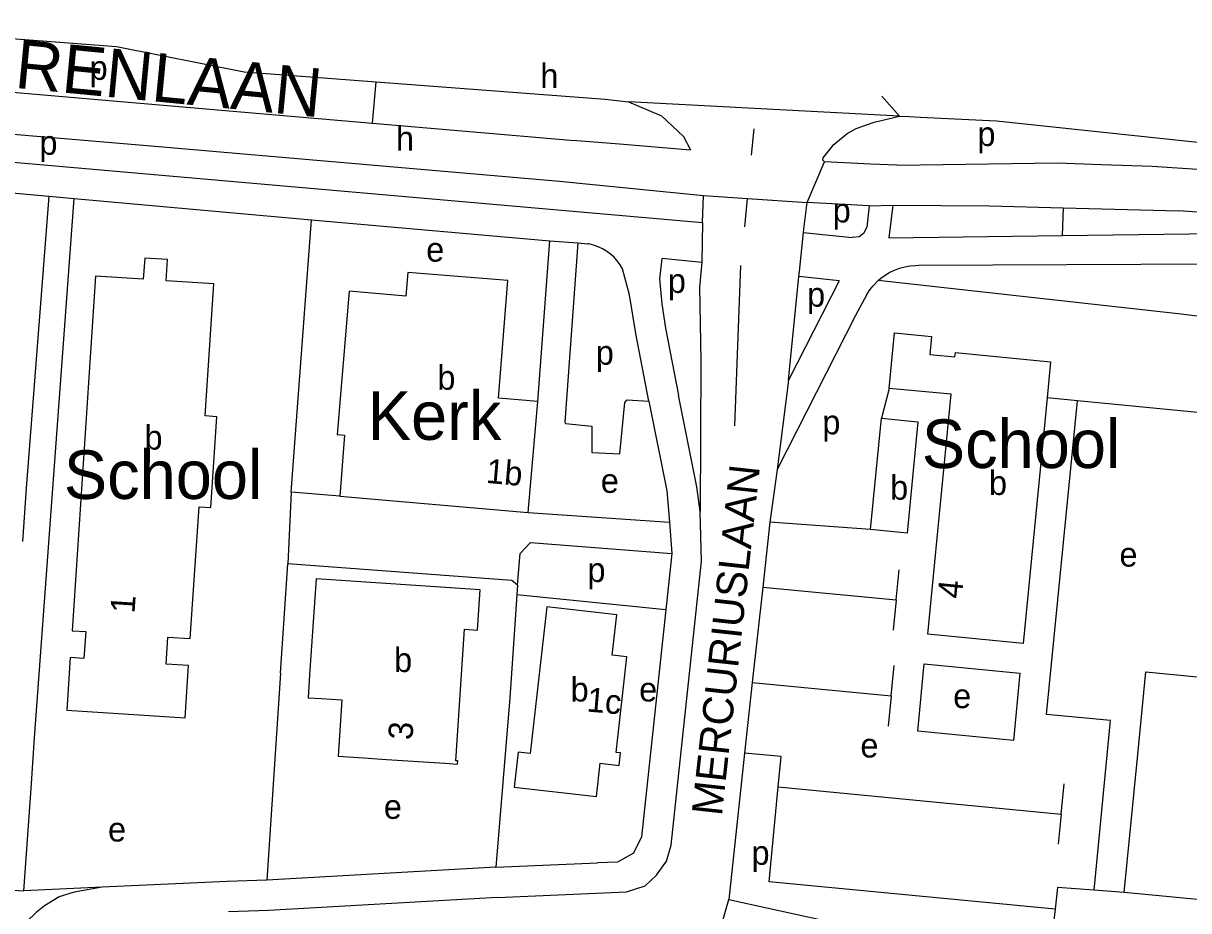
# Model space of a CAD drawing. Extents: x 161773 to 163836, y 384796 to 386521.
# Drawn here: x 162054.9 to 162246.8, y 386359.1 to 386505.2 of the extents above; entities that cross this region are included whole.
import ezdxf

# ---------------------------------------------------------------- set-up
doc = ezdxf.new("R2010")
doc.units = 0
for name, color, linetype in [('BLT_Basislijn', 7, 'Continuous'), ('BLT_Bebouwing', 7, 'Continuous'), ('BLT_Bebouwing_beschrifting', 7, 'Continuous'), ('BLT_Centroide', 7, 'Continuous'), ('BLT_Huisnummer', 7, 'Continuous'), ('BLT_Straatnaam', 7, 'Continuous'), ('BLT_Straatnaam_hoofdweg', 7, 'Continuous'), ('BLT_Vlakafsluiter', 7, 'Continuous')]:
    doc.layers.add(name, color=color, linetype=linetype)

msp = doc.modelspace()

# ---------------------------------------------------------------- linework, layer by layer
at = {"layer": 'BLT_Basislijn'}
for p, q in [((162112.37, 386488.77), (162112.99, 386495.59)), ((162077.31, 386491.77), (162112.37, 386488.77)), ((162002.79, 386491.19), (162077.21, 386484.92)), ((162112.37, 386488.77), (162145, 386485.99)), ((162174.81, 386483.48), (162175.23, 386487.81)), ((162145, 386485.99), (162146.03, 386485.91)), ((162146.03, 386485.91), (162153.05, 386485.37)), ((162077.21, 386484.92), (162143.18, 386479.23)), ((162153.05, 386485.37), (162164.77, 386484.39)), ((162004.3, 386481.62), (162059.08, 386476.74)), ((162143.18, 386479.23), (162166.9, 386476.88)), ((162059.08, 386476.74), (162055.37, 386428.67)), ((162059.08, 386476.74), (162063.26, 386476.36)), ((162060.46, 386438.36), (162063.26, 386476.36)), ((162063.26, 386476.36), (162102.35, 386472.88)), ((162166.71, 386472.43), (162166.9, 386476.88)), ((162173.67, 386471.69), (162174.12, 386476.38)), ((162194.19, 386475.17), (162183.94, 386475.71)), ((162194.19, 386475.17), (162198.04, 386475.28)), ((162226.12, 386474.85), (162225.92, 386470.26)), ((162226.12, 386474.85), (162245.23, 386474.34)), ((162098.98, 386428), (162102.35, 386472.88)), ((162102.35, 386472.88), (162141.6, 386469.4)), ((162266.83, 386472.75), (162245.23, 386474.34)), ((162166.71, 386472.43), (162166.62, 386465.81)), ((162183.33, 386470.77), (162191.39, 386469.94)), ((162225.92, 386470.26), (162252.74, 386470.61)), ((162139.58, 386442.97), (162141.6, 386469.4)), ((162141.6, 386469.4), (162146.17, 386469.04)), ((162146.17, 386469.04), (162147.85, 386468.91)), ((162172.06, 386438.96), (162173.06, 386465.35)), ((162202.35, 386465.37), (162252.34, 386465.63)), ((162189.2, 386462.82), (162182.58, 386463.52)), ((162189.2, 386462.82), (162180.89, 386446.48)), ((162193.8, 386460.58), (162191.89, 386457.08)), ((162191.89, 386457.08), (162178.99, 386431.72)), ((162180.89, 386446.48), (162178.99, 386431.72)), ((162197.46, 386445.11), (162196.17, 386440.2)), ((162223.39, 386391.42), (162228.45, 386443.04)), ((162228.45, 386443.04), (162223.47, 386443.53)), ((162178.99, 386431.72), (162177.82, 386423.1)), ((162055.37, 386428.67), (162054.77, 386419.92)), ((162138.03, 386424.67), (162161.31, 386423.05)), ((162166.57, 386416.66), (162166.33, 386424.82)), ((162161.31, 386423.05), (162161.69, 386417.91)), ((162177.82, 386423.1), (162176.64, 386412.37)), ((162194.41, 386421.85), (162177.82, 386423.1)), ((162161.69, 386417.91), (162160.68, 386408.62)), ((162097.25, 386398.22), (162098.45, 386416.24)), ((162198.62, 386410.27), (162199.1, 386415.24)), ((162136.26, 386412.69), (162136.15, 386411.09)), ((162160.68, 386408.62), (162136.15, 386411.09)), ((162176.64, 386412.37), (162174.92, 386396.68)), ((162176.64, 386412.37), (162198.62, 386410.27)), ((162198.62, 386410.27), (162198.14, 386405.29)), ((162097.25, 386398.22), (162094.98, 386364.12)), ((162197.79, 386394.49), (162198.26, 386399.46)), ((162174.92, 386396.68), (162173.66, 386385.07)), ((162174.9, 386396.68), (162197.79, 386394.49)), ((162197.79, 386394.49), (162197.31, 386389.51)), ((162173.66, 386385.07), (162171.05, 386360.94)), ((162054.99, 386362.39), (162056.16, 386379.24)), ((162179.2, 386379.49), (162225.77, 386375.02)), ((162225.77, 386375.02), (162226.25, 386380)), ((162225.77, 386375.02), (162225.29, 386370.04)), ((162132.71, 386366.26), (162149.44, 386366.99)), ((162132.71, 386366.26), (162094.98, 386364.12)), ((162088.45, 386363.89), (162067.88, 386362.97)), ((162094.98, 386364.12), (162088.45, 386363.89)), ((162052.3, 386362.57), (162054.99, 386362.39)), ((162067.88, 386362.97), (162054.99, 386362.39)), ((162132.96, 386361.27), (162154.23, 386362.2)), ((162225.19, 386362.94), (162224.77, 386359.37)), ((162231.2, 386362.5), (162225.19, 386362.94)), ((162236.18, 386362.13), (162231.2, 386362.5)), ((162224.77, 386359.37), (162223.74, 386350.72))]:
    msp.add_line(p, q, dxfattribs=at)
for points in [[(162046.31, 386502.96), (162053, 386502.69), (162070.25, 386501.37), (162091.27, 386497.24), (162112.99, 386495.59)], [(162003.09, 386498.13), (162015.49, 386497.13), (162077.31, 386491.77)], [(162112.99, 386495.59), (162150.72, 386492.73), (162154.52, 386492.27)], [(162154.52, 386492.27), (162159.98, 386489.95), (162163.58, 386486.57), (162164.77, 386484.39)], [(162186.79, 386482.38), (162186.56, 386482.67), (162186.61, 386483.04), (162188.36, 386485.27), (162190.56, 386487.07), (162192, 386487.88), (162195.01, 386488.92), (162199.14, 386489.93)], [(162199.14, 386489.93), (162200.76, 386489.85)], [(162200.76, 386489.85), (162202.54, 386489.78), (162215.14, 386489.16), (162251.92, 386485.23), (162266.39, 386484.28), (162278.05, 386481.5), (162301.92, 386479.18)], [(162002.53, 386486.84), (162003.63, 386486.7), (162166.71, 386472.43)], [(162198.78, 386481.86), (162194.36, 386482), (162186.79, 386482.38)], [(162198.78, 386481.86), (162225.1, 386482.22), (162232.41, 386481.99), (162240.77, 386481.69), (162249.05, 386481.16), (162254.69, 386480.86)], [(162183.33, 386470.77), (162183.38, 386471.29), (162183.94, 386475.71)], [(162194.19, 386475.17), (162193.77, 386471.65), (162193.25, 386470.61), (162192.51, 386470.08), (162191.39, 386469.94)], [(162198.04, 386475.28), (162197.39, 386469.88), (162225.92, 386470.26)], [(162198.04, 386475.28), (162214, 386475.17), (162226.12, 386474.85)], [(162182.58, 386463.52), (162182.72, 386464.33), (162183.33, 386470.77)], [(162146.17, 386469.04), (162144.04, 386439.55), (162144.16, 386439.31), (162148.52, 386438.87), (162148.49, 386434.54), (162153.11, 386434.3), (162153.92, 386442.78), (162154.34, 386443.19), (162157.89, 386443.01)], [(162153.55, 386464.76), (162153.15, 386465.45), (162152.68, 386466.09), (162152.15, 386466.68), (162151.57, 386467.21), (162150.93, 386467.69), (162150.25, 386468.09), (162149.53, 386468.43), (162148.78, 386468.69), (162148.01, 386468.88), (162147.85, 386468.91)], [(162166.62, 386465.81), (162160.01, 386466.46), (162159.63, 386463.13), (162160, 386459.01), (162160.65, 386455.03), (162162.79, 386443.97)], [(162166.62, 386465.81), (162166.22, 386461.74), (162166.42, 386449.71), (162166.33, 386424.82)], [(162195.65, 386462.84), (162196.09, 386463.23), (162196.8, 386463.75), (162197.56, 386464.21), (162198.35, 386464.59), (162199.18, 386464.9), (162200.03, 386465.13), (162200.89, 386465.29), (162201.77, 386465.36), (162202.35, 386465.37)], [(162157.89, 386443.01), (162155.73, 386454.15), (162154.69, 386460.49), (162153.55, 386464.76)], [(162180.89, 386446.48), (162182.58, 386463.52)], [(162193.8, 386460.58), (162194.28, 386461.32), (162194.83, 386462.01), (162195.65, 386462.84)], [(162252.58, 386456.45), (162245.53, 386457.32), (162195.65, 386462.84)], [(162252.58, 386456.45), (162251.06, 386440.84), (162228.45, 386443.04)], [(162166.33, 386424.82), (162165.81, 386428.92), (162162.79, 386443.97)], [(162157.89, 386443.01), (162160.85, 386428.21), (162161.31, 386423.05)], [(162056.16, 386379.24), (162056.72, 386387.55), (162060.46, 386438.36)], [(162098.98, 386428), (162098.45, 386416.24)], [(162107, 386427.35), (162098.98, 386428)], [(162136.26, 386412.69), (162136.68, 386417.92), (162138.4, 386419.75), (162161.69, 386417.91)], [(162136.26, 386412.69), (162135.35, 386413.47), (162098.45, 386416.24)], [(162154.23, 386362.2), (162157.3, 386363.22), (162159.16, 386364.97), (162160.81, 386367.28), (162161.55, 386369.88), (162166.57, 386416.66)], [(162136.15, 386411.09), (162134.99, 386394.18), (162132.71, 386366.26)], [(162160.68, 386408.62), (162156.68, 386371.28), (162155.35, 386368.56), (162152.71, 386367.08), (162149.44, 386366.99)], [(162231.2, 386362.5), (162233.9, 386390.4), (162223.39, 386391.42)], [(162179.2, 386379.49), (162179.68, 386384.49), (162173.66, 386385.07)], [(162224.77, 386359.37), (162177.71, 386363.88), (162179.2, 386379.49)], [(162067.88, 386362.97), (162063.25, 386362.18), (162060.78, 386361.41), (162058.37, 386359.89), (162056.99, 386358.79), (162055.44, 386357.35), (162053.96, 386354.94), (162052.75, 386352.1), (162052.68, 386351.64)], [(162132.96, 386361.27), (162095.26, 386359.13), (162088.68, 386358.9)], [(162156.67, 386349.55), (162163.16, 386350.3), (162166.96, 386352.02), (162169.55, 386355.75), (162171.05, 386360.94)], [(162171.05, 386360.94), (162207.82, 386352.89), (162223.74, 386350.72)]]:
    msp.add_lwpolyline(points, dxfattribs=at)
at = {"layer": 'BLT_Bebouwing'}
for p, q in [((162138.03, 386424.67), (162139.58, 386442.97)), ((162194.41, 386421.85), (162196.17, 386440.2)), ((162265.21, 386359.32), (162236.18, 386362.13))]:
    msp.add_line(p, q, dxfattribs=at)
for points in [[(162086.25, 386462.29), (162078.42, 386462.81), (162078.65, 386466.32), (162074.89, 386466.56), (162074.64, 386463.08), (162066.79, 386463.59), (162062.91, 386405.21), (162065.17, 386405.06), (162064.87, 386400.64), (162062.62, 386400.79), (162062.05, 386392.12), (162081.53, 386390.84), (162082.09, 386399.48), (162078.38, 386399.72), (162078.67, 386404.15), (162082.38, 386403.91), (162083.83, 386425.59), (162085.76, 386425.51), (162086.74, 386440.43), (162084.82, 386440.56), (162086.25, 386462.29)], [(162118.18, 386464.17), (162117.87, 386460.3), (162108.55, 386461.1)], [(162139.58, 386442.97), (162133.14, 386443.48), (162134.68, 386462.85), (162118.18, 386464.17)], [(162108.55, 386461.1), (162106.54, 386437.52), (162107.76, 386437.38)], [(162197.46, 386445.11), (162198.32, 386454.25), (162204.43, 386453.67), (162204.13, 386450.69), (162208.29, 386450.28), (162208.37, 386451), (162224.05, 386449.47), (162223.47, 386443.53)], [(162205.37, 386420.42), (162207.69, 386444.14), (162197.46, 386445.11)], [(162223.47, 386443.53), (162219.51, 386403.09), (162203.82, 386404.62), (162205.37, 386420.42)], [(162196.17, 386440.2), (162202.17, 386439.62), (162200.41, 386421.28), (162194.41, 386421.85)], [(162239.7, 386398.42), (162261.19, 386396.34), (162265.29, 386439.45)], [(162107.76, 386437.38), (162107, 386427.35)], [(162107, 386427.35), (162138.03, 386424.67)], [(162124.27, 386383.39), (162126.4, 386383.25), (162126.43, 386383.77), (162126.11, 386383.79), (162127.54, 386405.45), (162129.67, 386405.31), (162130.12, 386411.95), (162103.13, 386413.74), (162102.02, 386397.96)], [(162141.09, 386409.14), (162138.37, 386384.99), (162136.37, 386385.21), (162135.73, 386379.44), (162149.27, 386377.92), (162149.88, 386383.38), (162153, 386383.03), (162153.23, 386385.1), (162152.49, 386385.18), (162154.26, 386400.92), (162151.84, 386401.19), (162152.59, 386407.84), (162141.09, 386409.14)], [(162102.02, 386397.96), (162101.76, 386394.18), (162103.93, 386394.04), (162107.32, 386393.82), (162106.71, 386384.53), (162110.88, 386384.26)], [(162238.38, 386384.82), (162239.7, 386398.42)], [(162110.88, 386384.26), (162114.7, 386384.01)], [(162236.18, 386362.13), (162236.67, 386367.11), (162238.38, 386384.82)], [(162114.7, 386384.01), (162124.27, 386383.39)]]:
    msp.add_lwpolyline(points, dxfattribs=at)
msp.add_lwpolyline([(162203.2, 386399.73), (162219, 386398.19), (162217.93, 386387.13), (162202.17, 386388.67)], close=True, dxfattribs=at)
at = {"layer": 'BLT_Vlakafsluiter'}
for p, q in [((162199.14, 386489.93), (162154.52, 386492.27)), ((162196.25, 386493.24), (162199.14, 386489.93)), ((162183.94, 386475.71), (162186.79, 386482.38)), ((162166.9, 386476.88), (162174.12, 386476.38)), ((162174.12, 386476.38), (162183.94, 386475.71))]:
    msp.add_line(p, q, dxfattribs=at)

# ---------------------------------------------------------------- texts
at = {"layer": 'BLT_Bebouwing_beschrifting'}
for s, p in [('Kerk', (162111.59, 386436.63)), ('School', (162202.83, 386431.99)), ('School', (162061.55, 386426.9))]:
    msp.add_text(s, height=8, dxfattribs=at).set_placement(p)
at = {"layer": 'BLT_Centroide'}
for s, p in [('p', (162065.79, 386495.9)), ('h', (162140.02, 386494.57)), ('h', (162116.24, 386484.25)), ('p', (162211.99, 386485)), ('p', (162057.53, 386483.56)), ('p', (162188.16, 386472.42)), ('e', (162121.22, 386465.97)), ('p', (162161.01, 386460.82)), ('p', (162183.94, 386458.56)), ('p', (162149.15, 386449)), ('b', (162123.06, 386444.88)), ('p', (162186.45, 386437.54)), ('b', (162074.83, 386435.03)), ('e', (162149.97, 386427.9)), ('b', (162197.62, 386426.78)), ('b', (162213.89, 386427.56)), ('e', (162235.38, 386415.76)), ('p', (162147.77, 386413.23)), ('b', (162115.94, 386398.41)), ('b', (162145, 386393.55)), ('e', (162156.29, 386393.55)), ('e', (162208, 386392.46)), ('e', (162192.72, 386384.33)), ('e', (162114.25, 386374.23)), ('e', (162068.83, 386370.5)), ('p', (162174.79, 386366.66))]:
    msp.add_text(s, height=4, dxfattribs=at).set_placement(p)
at = {"layer": 'BLT_Huisnummer'}
for s, rotation, p in [('1b', 355.0619, (162130.99, 386429.55)), ('4', 84.4109, (162209.4, 386410.38)), ('1', 86.184, (162073.19, 386408)), ('1c', 355.0619, (162147.57, 386391.91)), ('3', 86.2012, (162118.94, 386387.13))]:
    msp.add_text(s, height=4, rotation=rotation, dxfattribs=at).set_placement(p)
at = {"layer": 'BLT_Straatnaam'}
msp.add_text('MERCURIUSLAAN', height=5, rotation=83.7798, dxfattribs=at).set_placement((162169.91, 386374.6))
at = {"layer": 'BLT_Straatnaam_hoofdweg'}
msp.add_text('STERRENLAAN', height=7.9999, rotation=354.4661, dxfattribs=at).set_placement((162024.93, 386497.35))

doc.saveas('drawing.dxf')
